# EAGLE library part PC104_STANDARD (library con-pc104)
PC/104 Standard 16 bit
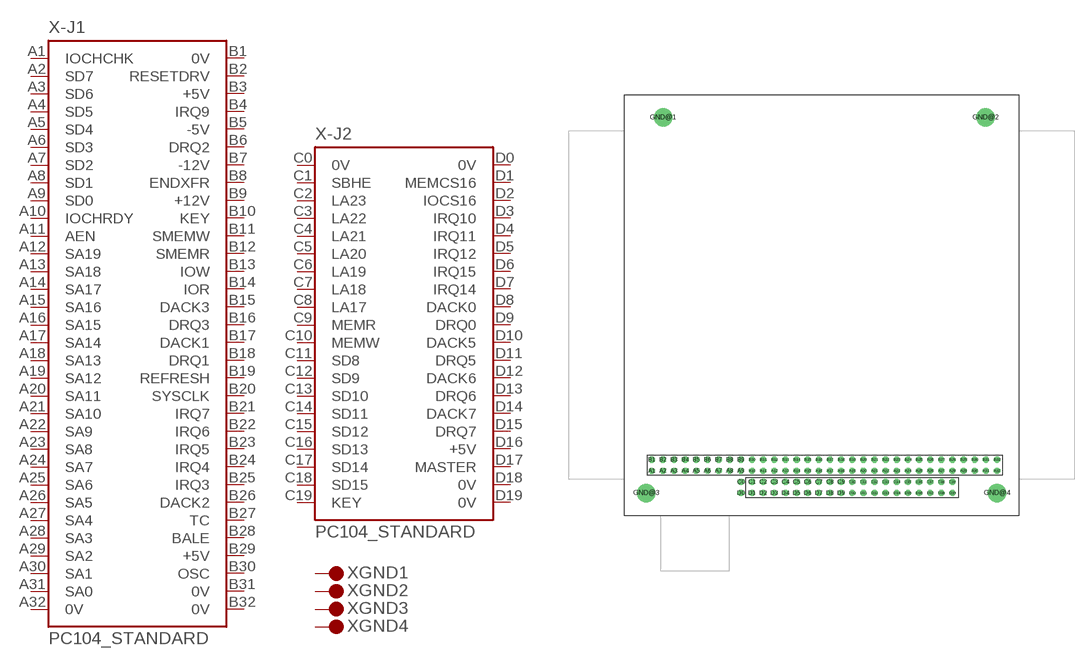
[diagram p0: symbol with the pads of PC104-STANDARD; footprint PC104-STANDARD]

Designator prefix X; gates -J1=PC104-J1 -J2=PC104-J2 GND1=PIN GND2=PIN GND3=PIN GND4=PIN

## PC104_STANDARD1  [PC104-STANDARD]
A1  -J1:IOCHCHK  pas
A2  -J1:SD7  pas
A3  -J1:SD6  pas
A4  -J1:SD5  pas
A5  -J1:SD4  pas
A6  -J1:SD3  pas
A7  -J1:SD2  pas
A8  -J1:SD1  pas
A9  -J1:SD0  pas
A10  -J1:IOCHRDY  pas
A11  -J1:AEN  pas
A12  -J1:SA19  pas
A13  -J1:SA18  pas
A14  -J1:SA17  pas
A15  -J1:SA16  pas
A16  -J1:SA15  pas
A17  -J1:SA14  pas
A18  -J1:SA13  pas
A19  -J1:SA12  pas
A20  -J1:SA11  pas
A21  -J1:SA10  pas
A22  -J1:SA9  pas
A23  -J1:SA8  pas
A24  -J1:SA7  pas
A25  -J1:SA6  pas
A26  -J1:SA5  pas
A27  -J1:SA4  pas
A28  -J1:SA3  pas
A29  -J1:SA2  pas
A30  -J1:SA1  pas
A31  -J1:SA0  pas
A32  -J1:0V  pas
B1  -J1:0V  pas
B2  -J1:RESETDRV  pas
B3  -J1:+5V  pas
B4  -J1:IRQ9  pas
B5  -J1:-5V  pas
B6  -J1:DRQ2  pas
B7  -J1:-12V  pas
B8  -J1:ENDXFR  pas
B9  -J1:+12V  pas
B10  -J1:KEY  pas
B11  -J1:SMEMW  pas
B12  -J1:SMEMR  pas
B13  -J1:IOW  pas
B14  -J1:IOR  pas
B15  -J1:DACK3  pas
B16  -J1:DRQ3  pas
B17  -J1:DACK1  pas
B18  -J1:DRQ1  pas
B19  -J1:REFRESH  pas
B20  -J1:SYSCLK  pas
B21  -J1:IRQ7  pas
B22  -J1:IRQ6  pas
B23  -J1:IRQ5  pas
B24  -J1:IRQ4  pas
B25  -J1:IRQ3  pas
B26  -J1:DACK2  pas
B27  -J1:TC  pas
B28  -J1:BALE  pas
B29  -J1:+5V  pas
B30  -J1:OSC  pas
B31  -J1:0V  pas
B32  -J1:0V  pas
C0  -J2:0V  pas
C1  -J2:SBHE  pas
C2  -J2:LA23  pas
C3  -J2:LA22  pas
C4  -J2:LA21  pas
C5  -J2:LA20  pas
C6  -J2:LA19  pas
C7  -J2:LA18  pas
C8  -J2:LA17  pas
C9  -J2:MEMR  pas
C10  -J2:MEMW  pas
C11  -J2:SD8  pas
C12  -J2:SD9  pas
C13  -J2:SD10  pas
C14  -J2:SD11  pas
C15  -J2:SD12  pas
C16  -J2:SD13  pas
C17  -J2:SD14  pas
C18  -J2:SD15  pas
C19  -J2:KEY  pas
D0  -J2:0V  pas
D1  -J2:MEMCS16  pas
D2  -J2:IOCS16  pas
D3  -J2:IRQ10  pas
D4  -J2:IRQ11  pas
D5  -J2:IRQ12  pas
D6  -J2:IRQ15  pas
D7  -J2:IRQ14  pas
D8  -J2:DACK0  pas
D9  -J2:DRQ0  pas
D10  -J2:DACK5  pas
D11  -J2:DRQ5  pas
D12  -J2:DACK6  pas
D13  -J2:DRQ6  pas
D14  -J2:DACK7  pas
D15  -J2:DRQ7  pas
D16  -J2:+5V  pas
D17  -J2:MASTER  pas
D18  -J2:0V  pas
D19  -J2:0V  pas
GND@1  GND1:1  pas
GND@2  GND2:1  pas
GND@3  GND3:1  pas
GND@4  GND4:1  pas

## Footprint PC104-STANDARD (pad centres in mm)
PC/104 Standard 16 bit
drill 0.9 pad 1.397 octagon: A1 6.35,10.16; A2 8.89,10.16; A3 11.43,10.16; A4 13.97,10.16; A5 16.51,10.16; A6 19.05,10.16; A7 21.59,10.16; A8 24.13,10.16; A9 26.67,10.16; A10 29.21,10.16; A11 31.75,10.16; A12 34.29,10.16; A13 36.83,10.16; A14 39.37,10.16; A15 41.91,10.16; A16 44.45,10.16; A17 46.99,10.16; A18 49.53,10.16; A19 52.07,10.16; A20 54.61,10.16; A21 57.15,10.16; A22 59.69,10.16; A23 62.23,10.16; A24 64.77,10.16; A25 67.31,10.16; A26 69.85,10.16; A27 72.39,10.16; A28 74.93,10.16; A29 77.47,10.16; A30 80.01,10.16; A31 82.55,10.16; A32 85.09,10.16; B1 6.35,12.7; B2 8.89,12.7; B3 11.43,12.7; B4 13.97,12.7; B5 16.51,12.7; B6 19.05,12.7; B7 21.59,12.7; B8 24.13,12.7; B9 26.67,12.7; B10 29.21,12.7; B11 31.75,12.7; B12 34.29,12.7; B13 36.83,12.7; B14 39.37,12.7; B15 41.91,12.7; B16 44.45,12.7; B17 46.99,12.7; B18 49.53,12.7; B19 52.07,12.7; B20 54.61,12.7; B21 57.15,12.7; B22 59.69,12.7; B23 62.23,12.7; B24 64.77,12.7; B25 67.31,12.7; B26 69.85,12.7; B27 72.39,12.7; B28 74.93,12.7; B29 77.47,12.7; B30 80.01,12.7; B31 82.55,12.7; B32 85.09,12.7; C0 26.67,7.62; C1 29.21,7.62; C2 31.75,7.62; C3 34.29,7.62; C4 36.83,7.62; C5 39.37,7.62; C6 41.91,7.62; C7 44.45,7.62; C8 46.99,7.62; C9 49.53,7.62; C10 52.07,7.62; C11 54.61,7.62; C12 57.15,7.62; C13 59.69,7.62; C14 62.23,7.62; C15 64.77,7.62; C16 67.31,7.62; C17 69.85,7.62; C18 72.39,7.62; C19 74.93,7.62; D0 26.67,5.08; D1 29.21,5.08; D2 31.75,5.08; D3 34.29,5.08; D4 36.83,5.08; D5 39.37,5.08; D6 41.91,5.08; D7 44.45,5.08; D8 46.99,5.08; D9 49.53,5.08; D10 52.07,5.08; D11 54.61,5.08; D12 57.15,5.08; D13 59.69,5.08; D14 62.23,5.08; D15 64.77,5.08; D16 67.31,5.08; D17 69.85,5.08; D18 72.39,5.08; D19 74.93,5.08
drill 3.2 pad 4 round: GND@1 8.9,90.8; GND@2 82.5,90.8; GND@3 5.1,5.1; GND@4 85.1,5.1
